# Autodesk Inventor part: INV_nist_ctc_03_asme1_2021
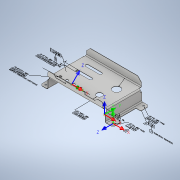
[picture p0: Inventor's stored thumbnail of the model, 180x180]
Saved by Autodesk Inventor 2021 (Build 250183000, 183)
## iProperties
Created: 2016-11
Part Number: INV_nist_ctc_03_asme1_2021
Material: Generic
Document SubType Name: Sheet Metal
Designer: t_liuje
Density: 1 g/cm^3
Sheet Metal Rule: 3-0.75in
Appearance: Default
Author: t_liuje
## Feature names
1. Hole1
2. Corner Round2
3. Corner Chamfer2
4. Mirror1
5. Mirror2
6. Corner Chamfer3
7. Corner Round4
8. Corner Chamfer5
9. Hole2
10. Hole3
11. Hole4
12. Corner Round5
13. Mirror4
14. Plate1
15. Plate2
16. Bend1
17. Plate3
18. Bend2
19. Plate4
20. Bend3
21. Plate6
22. Bend5
23. Plate7
24. Bend6
25. Plate8
26. Bend7
27. Plate10
28. Bend9
29. Plate11
30. Bend10
## Parameters: Thickness = 1.905 mm, BendRadius = 1.905 mm, BendReliefWidth = 1.905 mm, BendReliefDepth = 0.9525 mm, CornerReliefSize = 7.62 mm, SeamGap = 0.00508 mm, MinimumRemnant = 3.81 mm, TransitionRadius = 1.905 mm, JacobiRadiusSize = 1.905 mm, GapSize = 1.905 mm, d0 = 365.4552 mm, d1 = 223.52 mm, d2 = 0.9398 mm, d3 = 8.89 mm, d4 = 0.9398 mm, d5 = 8.89 mm, d6 = 89.3826 mm, d7 = 69.469 mm, d8 = 50.8 mm, d9 = 94.869 mm, d10 = 63.0174 mm, d11 = 38.1 mm, d12 = 15.875 mm, d13 = 38.1 mm, d14 = 37.719 mm, d17 = 44.45 mm, d20 = 25.4 mm, d24 = 88.9 mm, d25 = 19.05 mm, d26 = 51.2826 mm, d27 = 63.0174 mm, d30 = 63.0174 mm, d31 = 63.5 mm, d32 = 88.9 mm, d33 = 19.05 mm, d34 = 1.905 mm, d35 = 1.905 mm, d36 = 0.9525 mm, d37 = 3.81 mm, d38 = 1.905 mm, d39 = 20.828 mm, d40 = 90 deg, d41 = 6.35 mm, d42 = 7.62 mm, d43 = 1.905 mm, d44 = 1.905 mm, d46 = 49.022 mm, d47 = 1.905 mm, d48 = 1.905 mm, d49 = 0.9525 mm, d50 = 3.81 mm, d51 = 1.905 mm, d52 = 1.905 mm, d53 = 0.9525 mm, d54 = 3.81 mm, d55 = 1.905 mm, d56 = 19.05 mm, d57 = 90 deg, d58 = 6.35 mm, d59 = 7.62 mm, d60 = 1.905 mm, d61 = 1.905 mm, d62 = 31.75 mm, d63 = 57.15 mm, d76 = 1.905 mm, d77 = 1.905 mm, d78 = 0.9525 mm, d79 = 3.81 mm, d80 = 1.905 mm, d81 = 19.05 mm, d82 = 19.05 mm, d83 = 11.1252 mm, d84 = 19.05 mm, d85 = 9.525 mm, d86 = 6.35 mm, d87 = 82 deg, d88 = 1.905 mm, d89 = 0, d90 = 6.35 mm, d91 = 12.7 mm, d92 = 6.35 mm, d93 = 45 deg, d94 = 1.905 mm, d95 = 0.9525 mm, d96 = 3.81 mm, d97 = 1.905 mm, d98 = 50.8 mm, d99 = 90 deg, d100 = 6.35 mm, d101 = 7.62 mm, d102 = 1.905 mm, d103 = 1.905 mm, d104 = 25.4 mm, d105 = 6.35 mm, d106 = 45 deg, d107 = 1.905 mm, d108 = 0.9525 mm, d109 = 3.81 mm, d110 = 1.905 mm, d111 = 22.86 mm, d112 = 90 deg, d113 = 6.35 mm, d114 = 7.62 mm, d115 = 1.905 mm, d116 = 1.905 mm, d117 = 53.8226 mm, d118 = 15.24 mm, d129 = 182.7276 mm, d130 = 127 mm, d131 = 12.5984 mm, d132 = 1.905 mm, d133 = 1.905 mm, d134 = 0.9525 mm, d135 = 3.81 mm, d136 = 1.905 mm, d137 = 12.7 mm, d138 = 15.24 mm, d139 = 6.35 mm, d140 = 45 deg, d141 = 1.905 mm, d142 = 0.9525 mm, d143 = 3.81 mm, d144 = 1.905 mm, d145 = 65.7352 mm, d146 = 45 deg, d147 = 6.35 mm, d148 = 7.62 mm, d149 = 1.905 mm, d150 = 1.905 mm, d151 = 30.48 mm, d152 = 63.5 mm, d153 = 27.051 mm, d154 = 19.05 mm, d155 = 9.525 mm, d156 = 6.35 mm, d157 = 82 deg, d158 = 1.905 mm, d159 = 0, d160 = 44.45 mm, d161 = 12.7 mm, d162 = 4.7752 mm, d163 = 19.05 mm, d164 = 9.525 mm, d165 = 6.35 mm, d166 = 82 deg, d167 = 1.905 mm, d168 = 0, d169 = 16.764 mm, d170 = 44.45 mm, d171 = 4.7752 mm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
